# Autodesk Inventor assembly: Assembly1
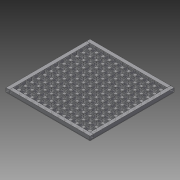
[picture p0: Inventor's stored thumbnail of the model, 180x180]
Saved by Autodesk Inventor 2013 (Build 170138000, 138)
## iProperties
Created: 2013-06
Part Number: Assembly1
Document SubType Name: Assembly
Designer: jpfenske
Author: jpfenske
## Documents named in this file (8)
- C:\Users\jpfenske\Documents\Things\Assembly1.iam
- C:\Users\jpfenske\Documents\Things\Part1.ipt
- C:\Users\jpfenske\Documents\Things\Part3.ipt
- C:\Users\jpfenske\Documents\Things\Part3_CPY.ipt
- C:\Users\jpfenske\Documents\Things\Part3_CPY1.ipt
- C:\Users\jpfenske\Documents\Things\Part3_CPY1_CPY.ipt
- C:\Users\jpfenske\Documents\Things\Part4.ipt
- C:\Users\jpfenske\Documents\Things\Part4_CPY.ipt
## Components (27 placed, 7 different names)
1. Part1:1 — Flush:1, Flush:2, Flush:3, Mate:1, Flush:4, Mate:2, Mate:3, Mate:5, Flush:5, Mate:6, Mate:7, Mate:8, Mate:9, Mate:6
2. Part3:1 — Flush:1, Flush:2, Flush:3, Mate:10
3. Part3_CPY:1 — Mate:1, Flush:4, Mate:2, Mate:14
4. Part3_CPY1:1 — Mate:3, Mate:5, Flush:5, Mate:13
5. Part3_CPY1_CPY:1 — Mate:6, Mate:7, Mate:8, Mate:11
6. Part4:1 — Mate:9, Mate:10, Mate:11
7. Part4:2
8. Part4:3
9. Part4:4
10. Part4:5
11. Part4:6
12. Part4:7
13. Part4:8
14. Part4:9
15. Part4:10
16. Part4:11
17. Part4_CPY:1 — Mate:13, Mate:6, Mate:14
18. Part4_CPY:2
19. Part4_CPY:3
20. Part4_CPY:4
21. Part4_CPY:5
22. Part4_CPY:6
23. Part4_CPY:7
24. Part4_CPY:8
25. Part4_CPY:9
26. Part4_CPY:10
27. Part4_CPY:11
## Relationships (18: Mate 13, Flush 5)
- Flush:1: Part1:1 ↔ Part3:1
- Flush:2: Part1:1 ↔ Part3:1
- Flush:3: Part1:1 ↔ Part3:1
- Mate:1: Part1:1 ↔ Part3_CPY:1
- Flush:4: Part1:1 ↔ Part3_CPY:1
- Mate:2: Part1:1 ↔ Part3_CPY:1
- Mate:3: Part1:1 ↔ Part3_CPY1:1
- Mate:5: Part1:1 ↔ Part3_CPY1:1
- Flush:5: Part1:1 ↔ Part3_CPY1:1
- Mate:6: Part1:1 ↔ Part3_CPY1_CPY:1
- Mate:7: Part1:1 ↔ Part3_CPY1_CPY:1
- Mate:8: Part1:1 ↔ Part3_CPY1_CPY:1
- Mate:9: Part1:1 ↔ Part4:1
- Mate:10: Part3:1 ↔ Part4:1
- Mate:11: Part3_CPY1_CPY:1 ↔ Part4:1
- Mate:13: Part3_CPY1:1 ↔ Part4_CPY:1
- Mate:6: Part1:1 ↔ Part4_CPY:1
- Mate:14: Part3_CPY:1 ↔ Part4_CPY:1
